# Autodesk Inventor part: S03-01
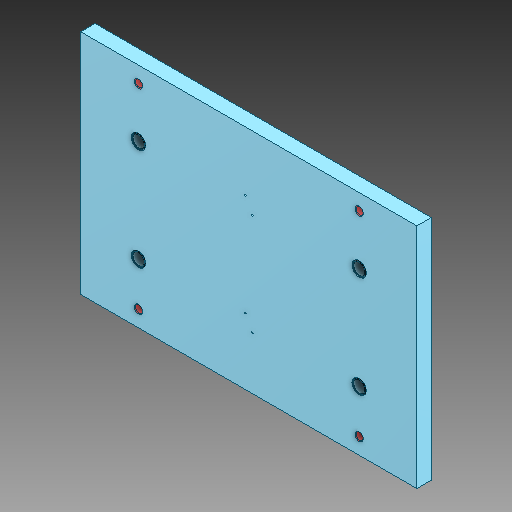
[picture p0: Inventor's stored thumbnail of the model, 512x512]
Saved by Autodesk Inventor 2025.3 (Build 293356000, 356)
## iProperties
Created: 2025-04
Part Number: S03-01
Material: Všeobecné
Document SubType Name: Modeling
Designer: Patrik
Density: 1 g/cm^3
Appearance: Výchozí
Description: Vyhazovaci deska
Mass: 1782.8 g
Surface Area: 2387.93 cm^2
Volume: 1782.8 cm^3
Stock Number: F 90/396 396/268/1730
User Status: 1730
Author: Patrik
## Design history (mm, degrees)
feature "Base1"
feature "Vyřezání2"
feature "Vyřezání7"
node "Těleso1"
feature "Plocha3"
node "Povrch3"
feature "Plocha13"
node "Povrch13"
